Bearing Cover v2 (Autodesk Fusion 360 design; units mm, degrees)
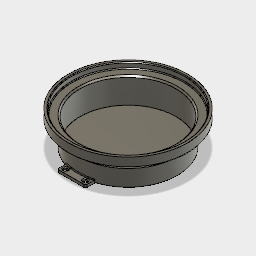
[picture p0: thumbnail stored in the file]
box_primitive "BoxPrimitive1" DistanceX 40 DistanceY 10 DistanceZ 1 OffsetDistanceX 0 OffsetDistanceY 0
cylinder_primitive "CylinderPrimitive1" Height 9 Diameter 35
cylinder_primitive "CylinderPrimitive3" Height 3 Diameter 42.1
cylinder_primitive "CylinderPrimitive4" Height -2 Diameter 40
cylinder_primitive "CylinderPrimitive5" Height -9 Diameter 33.9
chamfer "Chamfer1" distance 3
chamfer "Chamfer2" distance 0.25
chamfer "Chamfer3" distance 0.5
chamfer "Chamfer4" distance 0.25
chamfer "Chamfer5" distance 0.25
cylinder_primitive "CylinderPrimitive6" Height -1 Diameter 1.5
cylinder_primitive "CylinderPrimitive7" Height -1 Diameter 1.5
cylinder_primitive "CylinderPrimitive8" Height -1 Diameter 1.5
cylinder_primitive "CylinderPrimitive9" Height -1 Diameter 1.5
chamfer "Chamfer6" distance 0.25
chamfer "Chamfer7" distance 0.25
chamfer "Chamfer8" distance 0.25
chamfer "Chamfer9" distance 0.25
chamfer "Chamfer10" distance 0.5
chamfer "Chamfer11" distance 0.5
combine "Combine1"
chamfer "Chamfer12" distance 0.25
chamfer "Chamfer13" distance 0.25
